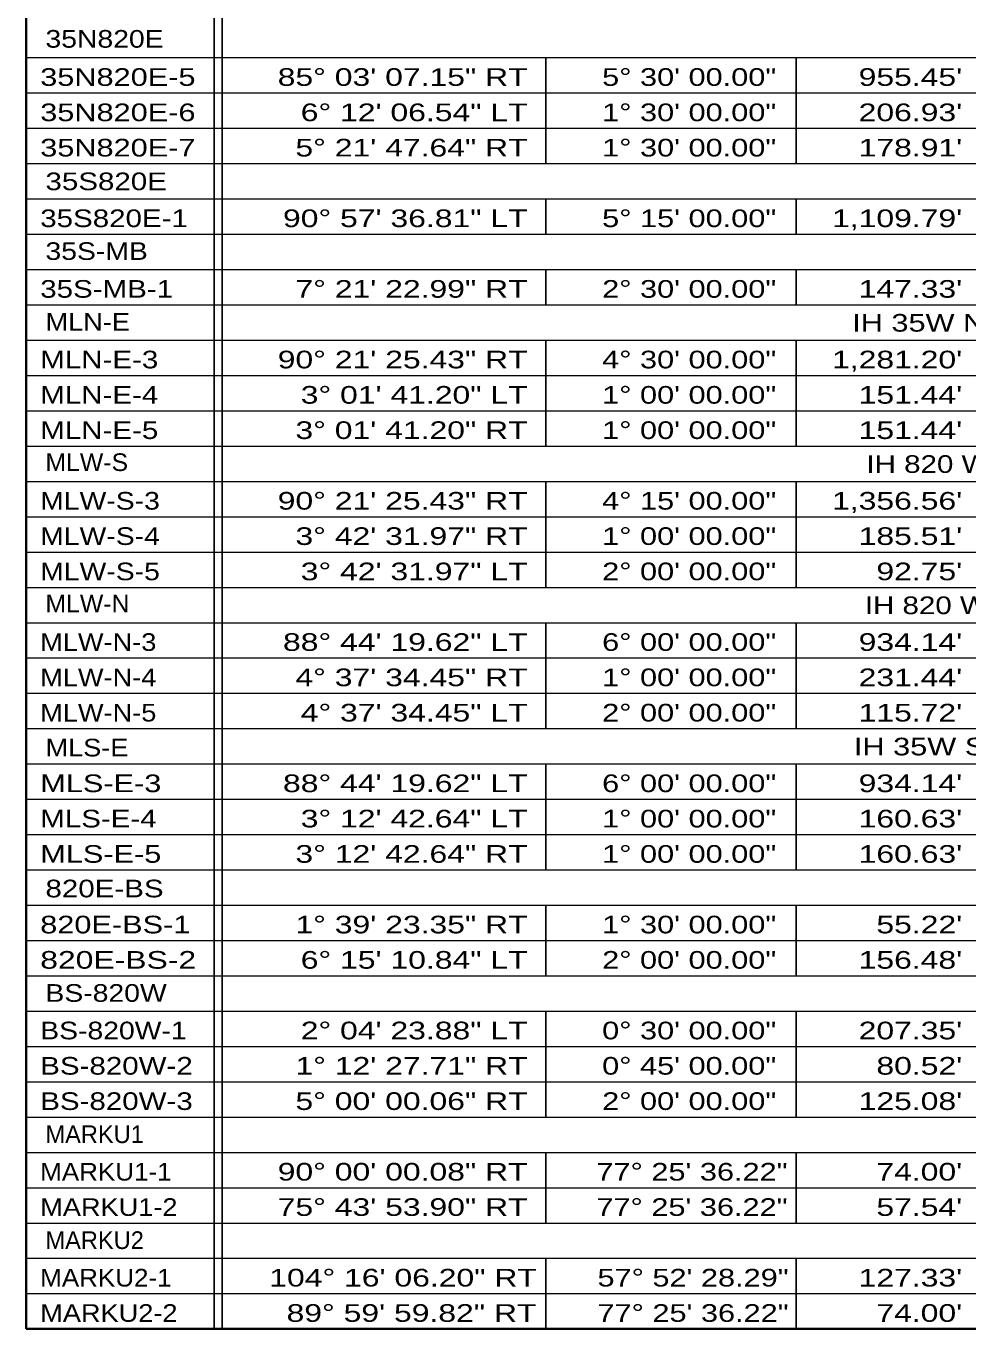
# Model space of a CAD drawing. Extents: x 1953053 to 1967065, y 7363860 to 7371201.
# Drawn here: x 1955933 to 1956574, y 7367608 to 7368493 of the extents above; entities that cross this region are included whole.
import ezdxf
from ezdxf.enums import TextEntityAlignment as Align

# ---------------------------------------------------------------- set-up
doc = ezdxf.new("R2010")
doc.units = 0
doc.header["$LTSCALE"] = 4.8
doc.layers.add('10', color=7, linetype='Continuous')
doc.layers.add('12', color=7, linetype='Continuous', lineweight=25)

msp = doc.modelspace()

# ---------------------------------------------------------------- linework, layer by layer
at = {"layer": '12', "lineweight": 35}
for p, q in [((1955933.385, 7370164.879), (1955933.385, 7367607.746)), ((1955933.385, 7367607.746), (1957656.717, 7367607.746))]:
    msp.add_line(p, q, dxfattribs=at)
at = {"layer": '12'}
for p, q in [((1956061.23, 7370136.079), (1956061.23, 7367607.746)), ((1956066.717, 7370136.079), (1956066.717, 7367607.746)), ((1956286.717, 7368471.746), (1956286.717, 7368399.746)), ((1956456.717, 7368471.746), (1956456.717, 7368399.746)), ((1956286.717, 7368375.746), (1956286.717, 7368351.746)), ((1956456.717, 7368375.746), (1956456.717, 7368351.746)), ((1956286.717, 7368327.746), (1956286.717, 7368303.746)), ((1956456.717, 7368327.746), (1956456.717, 7368303.746)), ((1956286.717, 7368279.746), (1956286.717, 7368207.746)), ((1956456.717, 7368279.746), (1956456.717, 7368207.746)), ((1956286.717, 7368183.746), (1956286.717, 7368111.746)), ((1956456.717, 7368183.746), (1956456.717, 7368111.746)), ((1956286.717, 7368087.746), (1956286.717, 7368015.746)), ((1956456.717, 7368087.746), (1956456.717, 7368015.746)), ((1956286.717, 7367991.746), (1956286.717, 7367919.746)), ((1956456.717, 7367991.746), (1956456.717, 7367919.746)), ((1956286.717, 7367895.746), (1956286.717, 7367847.746)), ((1956456.717, 7367895.746), (1956456.717, 7367847.746)), ((1956286.717, 7367823.746), (1956286.717, 7367751.746)), ((1956456.717, 7367823.746), (1956456.717, 7367751.746)), ((1956286.717, 7367727.746), (1956286.717, 7367679.746)), ((1956456.717, 7367727.746), (1956456.717, 7367679.746)), ((1956286.717, 7367655.746), (1956286.717, 7367607.746)), ((1956456.717, 7367655.746), (1956456.717, 7367607.746))]:
    msp.add_line(p, q, dxfattribs=at)
at = {"layer": '12', "lineweight": 13}
for p, q in [((1955933.385, 7368471.746), (1957656.717, 7368471.746)), ((1955933.385, 7368447.746), (1957656.717, 7368447.746)), ((1955933.385, 7368423.746), (1957656.717, 7368423.746)), ((1955933.385, 7368399.746), (1957656.717, 7368399.746)), ((1955933.385, 7368375.746), (1957656.717, 7368375.746)), ((1955933.385, 7368351.746), (1957656.717, 7368351.746)), ((1955933.385, 7368327.746), (1957656.717, 7368327.746)), ((1955933.385, 7368303.746), (1957656.717, 7368303.746)), ((1955933.385, 7368279.746), (1957656.717, 7368279.746)), ((1955933.385, 7368255.746), (1957656.717, 7368255.746)), ((1955933.385, 7368231.746), (1957656.717, 7368231.746)), ((1955933.385, 7368207.746), (1957656.717, 7368207.746)), ((1955933.385, 7368183.746), (1957656.717, 7368183.746)), ((1955933.385, 7368159.746), (1957656.717, 7368159.746)), ((1955933.385, 7368135.746), (1957656.717, 7368135.746)), ((1955933.385, 7368111.746), (1957656.717, 7368111.746)), ((1955933.385, 7368087.746), (1957656.717, 7368087.746)), ((1955933.385, 7368063.746), (1957656.717, 7368063.746)), ((1955933.385, 7368039.746), (1957656.717, 7368039.746)), ((1955933.385, 7368015.746), (1957656.717, 7368015.746)), ((1955933.385, 7367991.746), (1957656.717, 7367991.746)), ((1955933.385, 7367967.746), (1957656.717, 7367967.746)), ((1955933.385, 7367943.746), (1957656.717, 7367943.746)), ((1955933.385, 7367919.746), (1957656.717, 7367919.746)), ((1955933.385, 7367895.746), (1957656.717, 7367895.746)), ((1955933.385, 7367871.746), (1957656.717, 7367871.746)), ((1955933.385, 7367847.746), (1957656.717, 7367847.746)), ((1955933.385, 7367823.746), (1957656.717, 7367823.746)), ((1955933.385, 7367799.746), (1957656.717, 7367799.746)), ((1955933.385, 7367775.746), (1957656.717, 7367775.746)), ((1955933.385, 7367751.746), (1957656.717, 7367751.746)), ((1955933.385, 7367727.746), (1957656.717, 7367727.746)), ((1955933.385, 7367703.746), (1957656.717, 7367703.746)), ((1955933.385, 7367679.746), (1957656.717, 7367679.746)), ((1955933.385, 7367655.746), (1957656.717, 7367655.746)), ((1955933.385, 7367631.746), (1957656.717, 7367631.746))]:
    msp.add_line(p, q, dxfattribs=at)

# ---------------------------------------------------------------- texts
at = {"layer": '10'}
for s, width, p in [('35N820E', 1.2, (1955946.57, 7368478.505)), ('35N820E-5', 1.3, (1955943.011, 7368452.569)), ('35N820E-6', 1.3, (1955943.011, 7368428.569)), ('35N820E-7', 1.3, (1955943.011, 7368404.569)), ('35S820E', 1.25, (1955946.57, 7368381.665)), ('35S820E-1', 1.25, (1955943.011, 7368356.569)), ('35S-MB', 1.2, (1955946.57, 7368334.275)), ('35S-MB-1', 1.25, (1955943.011, 7368308.569)), ('MLN-E', 1.15, (1955946.57, 7368286.199)), ('MLN-E-3', 1.25, (1955943.011, 7368260.569)), ('MLN-E-4', 1.25, (1955943.011, 7368236.569)), ('MLN-E-5', 1.25, (1955943.011, 7368212.569)), ('MLW-S', 1.05, (1955946.57, 7368190.809)), ('MLW-S-3', 1.2, (1955943.011, 7368164.569)), ('MLW-S-4', 1.2, (1955943.011, 7368140.569)), ('MLW-S-5', 1.2, (1955943.011, 7368116.569)), ('MLW-N', 1.05, (1955946.57, 7368094.733)), ('MLW-N-3', 1.15, (1955943.011, 7368068.569)), ('MLW-N-4', 1.15, (1955943.011, 7368044.569)), ('MLW-N-5', 1.15, (1955943.011, 7368020.569)), ('MLS-E', 1.15, (1955946.57, 7367996.833)), ('MLS-E-3', 1.3, (1955943.011, 7367972.569)), ('MLS-E-4', 1.25, (1955943.011, 7367948.569)), ('MLS-E-5', 1.3, (1955943.011, 7367924.569)), ('820E-BS', 1.25, (1955946.57, 7367901.063)), ('820E-BS-1', 1.3, (1955943.011, 7367876.569)), ('820E-BS-2', 1.35, (1955943.011, 7367852.569)), ('BS-820W', 1.2, (1955946.57, 7367830.076)), ('BS-820W-1', 1.2, (1955943.011, 7367804.569)), ('BS-820W-2', 1.25, (1955943.011, 7367780.569)), ('BS-820W-3', 1.25, (1955943.011, 7367756.569)), ('MARKU1-1', 1.1, (1955943.006, 7367708.573)), ('MARKU1-2', 1.15, (1955943.006, 7367684.573)), ('MARKU2-1', 1.1, (1955943.006, 7367636.573)), ('MARKU2-2', 1.15, (1955943.006, 7367612.573))]:
    msp.add_text(s, height=12, dxfattribs=dict(at, width=width)).set_placement(p)
for s, width, p in [('85° 03\' 07.15" RT', 1.35, (1956274.244, 7368452.569)), ('5° 30\' 00.00"', 1.3, (1956443.239, 7368452.569)), ("955.45'", 1.35, (1956569.649, 7368452.569)), ('6° 12\' 06.54" LT', 1.35, (1956274.244, 7368428.569)), ('1° 30\' 00.00"', 1.3, (1956443.239, 7368428.569)), ("206.93'", 1.35, (1956569.649, 7368428.569)), ('5° 21\' 47.64" RT', 1.35, (1956274.244, 7368404.569)), ('1° 30\' 00.00"', 1.3, (1956443.239, 7368404.569)), ("178.91'", 1.35, (1956569.649, 7368404.569)), ('90° 57\' 36.81" LT', 1.35, (1956274.244, 7368356.569)), ('5° 15\' 00.00"', 1.3, (1956443.239, 7368356.569)), ("1,109.79'", 1.35, (1956569.649, 7368356.569)), ('7° 21\' 22.99" RT', 1.35, (1956274.244, 7368308.569)), ('2° 30\' 00.00"', 1.3, (1956443.239, 7368308.569)), ("147.33'", 1.35, (1956569.649, 7368308.569)), ('90° 21\' 25.43" RT', 1.35, (1956274.244, 7368260.569)), ('4° 30\' 00.00"', 1.3, (1956443.239, 7368260.569)), ("1,281.20'", 1.35, (1956569.649, 7368260.569)), ('3° 01\' 41.20" LT', 1.35, (1956274.244, 7368236.569)), ('1° 00\' 00.00"', 1.3, (1956443.239, 7368236.569)), ("151.44'", 1.35, (1956569.649, 7368236.569)), ('3° 01\' 41.20" RT', 1.35, (1956274.244, 7368212.569)), ('1° 00\' 00.00"', 1.3, (1956443.239, 7368212.569)), ("151.44'", 1.35, (1956569.649, 7368212.569)), ('90° 21\' 25.43" RT', 1.35, (1956274.244, 7368164.569)), ('4° 15\' 00.00"', 1.3, (1956443.239, 7368164.569)), ("1,356.56'", 1.35, (1956569.649, 7368164.569)), ('3° 42\' 31.97" RT', 1.35, (1956274.244, 7368140.569)), ('1° 00\' 00.00"', 1.3, (1956443.239, 7368140.569)), ("185.51'", 1.35, (1956569.649, 7368140.569)), ('3° 42\' 31.97" LT', 1.35, (1956274.244, 7368116.569)), ('2° 00\' 00.00"', 1.3, (1956443.239, 7368116.569)), ("92.75'", 1.35, (1956569.649, 7368116.569)), ('88° 44\' 19.62" LT', 1.35, (1956274.244, 7368068.569)), ('6° 00\' 00.00"', 1.3, (1956443.239, 7368068.569)), ("934.14'", 1.35, (1956569.649, 7368068.569)), ('4° 37\' 34.45" RT', 1.35, (1956274.244, 7368044.569)), ('1° 00\' 00.00"', 1.3, (1956443.239, 7368044.569)), ("231.44'", 1.35, (1956569.649, 7368044.569)), ('4° 37\' 34.45" LT', 1.35, (1956274.244, 7368020.569)), ('2° 00\' 00.00"', 1.3, (1956443.239, 7368020.569)), ("115.72'", 1.35, (1956569.649, 7368020.569)), ('88° 44\' 19.62" LT', 1.35, (1956274.244, 7367972.569)), ('6° 00\' 00.00"', 1.3, (1956443.239, 7367972.569)), ("934.14'", 1.35, (1956569.649, 7367972.569)), ('3° 12\' 42.64" LT', 1.35, (1956274.244, 7367948.569)), ('1° 00\' 00.00"', 1.3, (1956443.239, 7367948.569)), ("160.63'", 1.35, (1956569.649, 7367948.569)), ('3° 12\' 42.64" RT', 1.35, (1956274.244, 7367924.569)), ('1° 00\' 00.00"', 1.3, (1956443.239, 7367924.569)), ("160.63'", 1.35, (1956569.649, 7367924.569)), ('1° 39\' 23.35" RT', 1.35, (1956274.244, 7367876.569)), ('1° 30\' 00.00"', 1.3, (1956443.239, 7367876.569)), ("55.22'", 1.35, (1956569.649, 7367876.569)), ('6° 15\' 10.84" LT', 1.35, (1956274.244, 7367852.569)), ('2° 00\' 00.00"', 1.3, (1956443.239, 7367852.569)), ("156.48'", 1.35, (1956569.649, 7367852.569)), ('2° 04\' 23.88" LT', 1.35, (1956274.244, 7367804.569)), ('0° 30\' 00.00"', 1.3, (1956443.239, 7367804.569)), ("207.35'", 1.35, (1956569.649, 7367804.569)), ('1° 12\' 27.71" RT', 1.35, (1956274.244, 7367780.569)), ('0° 45\' 00.00"', 1.3, (1956443.239, 7367780.569)), ("80.52'", 1.35, (1956569.649, 7367780.569)), ('5° 00\' 00.06" RT', 1.35, (1956274.244, 7367756.569)), ('2° 00\' 00.00"', 1.3, (1956443.239, 7367756.569)), ("125.08'", 1.35, (1956569.649, 7367756.569)), ('90° 00\' 00.08" RT', 1.35, (1956274.239, 7367708.573)), ('77° 25\' 36.22"', 1.3, (1956450.936, 7367708.573)), ("74.00'", 1.35, (1956569.644, 7367708.573)), ('75° 43\' 53.90" RT', 1.35, (1956274.239, 7367684.573)), ('77° 25\' 36.22"', 1.3, (1956450.936, 7367684.573)), ("57.54'", 1.35, (1956569.644, 7367684.573)), ('104° 16\' 06.20" RT', 1.35, (1956280.554, 7367636.573)), ('57° 52\' 28.29"', 1.3, (1956451.663, 7367636.573)), ("127.33'", 1.35, (1956569.644, 7367636.573)), ('89° 59\' 59.82" RT', 1.35, (1956280.266, 7367612.573)), ('77° 25\' 36.22"', 1.3, (1956451.663, 7367612.573)), ("74.00'", 1.35, (1956569.644, 7367612.573))]:
    msp.add_text(s, height=12, dxfattribs=dict(at, width=width)).set_placement(p, align=Align.RIGHT)
for s, width, p in [('IH 35W NB DIRECT CONNECTOR TO IH 820 EB MANAGED LANES (MLN-E)', 1.3, (1956861.718, 7368285.54)), ('IH 820 WB DIRECT CONNECTOR TO IH 35W SB MANAGED LANES (MLW-S)', 1.25, (1956861.718, 7368189.54)), ('IH 820 WB DIRECT CONNECTOR TO IH 35W NB MANAGED LANES (MLW-N)', 1.25, (1956861.718, 7368093.54)), ('IH 35W SB DIRECT CONNECTOR TO IH 820 EB MANAGED LANES (MLS-E)', 1.3, (1956861.718, 7367997.54))]:
    msp.add_text(s, height=12, dxfattribs=dict(at, width=width)).set_placement(p, align=Align.CENTER)
for s, p in [('MARKU1', (1955946.57, 7367734.076)), ('MARKU2', (1955946.57, 7367662.076))]:
    msp.add_text(s, height=12, dxfattribs=at).set_placement(p)

doc.saveas('drawing.dxf')
